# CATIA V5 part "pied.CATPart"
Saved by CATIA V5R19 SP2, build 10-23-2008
Part number: pose pied
Bounding box of the stored display mesh (mm): x -13.5 to 13.5, y -11.25 to 6.521, z -13.5 to 67.5
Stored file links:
  F:\Travaux\Modélisations\CFAO_2011\MMS\MMS_GR2\AA_OK\jboiteux\Catia\pied.CATPart
  F:\Travaux\Modélisations\CFAO_2011\MMS\MMS_GR2\AA_OK\jboiteux\Catia\boulon gauche.CATPart
  F:\Travaux\Modélisations\CFAO_2011\MMS\MMS_GR2\AA_OK\jboiteux\Catia\bati.CATPart
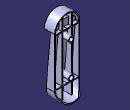
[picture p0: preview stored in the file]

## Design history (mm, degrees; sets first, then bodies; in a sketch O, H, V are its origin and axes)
Parameters
  `rayon ext` = 4.5 mm {= External.royontubebati /2}
External parameters (linked from other documents)
  External.rayontube = 9 mm
  External.royontubebati = 9 mm
Body1 (main body)
  Sketch1 on zx-plane, origin (0, 0, 0), H (-1, 0, 0), V (0, 0, 1)
    arc A1 centre (0, 54) radius 13.5 from (13.5, 54) to (-13.5, 54) ccw
    point P1 (0, 54)
    point P2 (0, 67.5)
    arc A2 centre (0, 0) radius 13.5 from (-13.5, 0) to (13.5, 0) ccw
    point P3 (0, 0)
    point P4 (0, -13.5)
    line L1 (-13.5, 54) -> (-13.5, 0)
    point P5 (-13.5, 0)
    line L2 (13.5, 0) -> (13.5, 54)
    point P7 (13.5, 0)
    point P9 (-13.5, 0)
    point P10 (13.5, 0)
    radius A1 = 13.5 {= `rayon ext` *3}
    distance A1 A2 = 81 {= `rayon ext` *18}
    distance P3 O = 0
    distance L2 L1 = 27 {= 6*`rayon ext`}
    radius A2 = 13.5 {= 3*`rayon ext`}
    coincidence: P1 V, A1 P2, P2 V, P3 V, A2 P4, P4 V, P5 A2, L2 P10, L1 P9, P5 P9, P7 P10
    tangency: L1 A2, L2 A1
  Sketch2 on yz-plane, origin (0, 0, 0), H (0, 1, 0), V (0, 0, 1)
    line L1 (6.5212, -13.5) -> (-10.3538, -13.5)
    line L2 (-10.3538, -13.5) -> (-4.5, 53.4095)
    point P3 (-4.5, 53.4095)
    line L3 (-4.5, 53.4095) -> (-11.25, 54)
    line L4 (-11.25, 54) -> (-11.25, 67.5)
    line L5 (-11.25, 67.5) -> (0, 67.5)
    point P6 (0, 67.5)
    line L6 (0, 67.5) -> (0, 0)
    point P7 (0, 0)
    line L7 (6.5212, -11.25) -> (6.5212, -13.5)
    point P8 (6.5212, -11.25)
    spline S1 through (6.5212, -11.25) (2.0212, -6.75) (0, 0)
    point P9 (6.5212, -11.25)
    point P10 (0, 0)
    point P11 (2.0212, -6.75)
    distance L5 L1 = 81 {= 18*`rayon ext`}
    angle L4 L3 = 95
    distance L5 H = 67.5 {= 15*`rayon ext`}
    distance P3 L4 = 6.75 {= `rayon ext` *3/2}
    length L1 = 16.875 {= `rayon ext` *15/4}
    length L5 = 11.25 {= `rayon ext`* 5/2}
    length L7 = 2.25 {= `rayon ext` /2}
    distance P7 O = 0
    length L4 = 13.5 {= 3*`rayon ext`}
    distance L7 P11 = 4.5 {= `rayon ext`}
    distance P11 L1 = 6.75 {= `rayon ext` *1.5}
    horizontal: L1 H, L5 H
    perpendicularity: L3 L2
    vertical: L4 V, L7 V
    coincidence: P6 V, P9 P8, P10 O
  SolidCombine1: FirstComponentDirection Sketch1, FirstComponentProfile Sketch1, SecondComponentDirection Sketch2, SecondComponentProfile Sketch2
  Sketch3 on face of SolidCombine1 from Sketch2.L4, origin (0, -11.25, 0), H (1, 0, 0), V (0, 0, 1)
    arc A1 centre (0, 42.0941) radius 18 from (13.5, 54) to (-13.5, 54) ccw
    point P1 (0, 42.0941)
    reference projected point E1 (13.5, 54) from vertex [face of SolidCombine1 from Sketch2.L4 | face of SolidCombine1 from Sketch1.A1 | face of SolidCombine1 from Sketch2.L3 | face of SolidCombine1 from Sketch1.L1]
    projected line E2 (-13.5, 53.4095) -> (13.5, 53.4095) from edge [face of SolidCombine1 from Sketch2.L2 | face of SolidCombine1 from Sketch2.L3]
    line L1 (-13.5, 53.4095) -> (-13.5, 54)
    line L2 (13.5, 53.4095) -> (13.5, 54)
    distance A1 E1 = 0
    radius A1 = 18 {= 4*`rayon ext`}
    angle L1 E2 = 90
    angle E2 L2 = 90
    coincidence: P1 V
  Pocket1: profile Sketch3, direction (0, 1, 0), up to face of SolidCombine1 from Sketch2.L2
  Shell1: ExtOffset 0, Face (face of SolidCombine1 from Sketch2.L6; face of SolidCombine1 from Sketch2.S1; face of SolidCombine1 from Sketch2.L7), IntOffset 1
  Sketch4 on face of SolidCombine1 from Sketch2.L6, origin (0, 0, 0), H (-1, 0, 0), V (0, 0, 1)
    projected arc E1 centre (0, 54) radius 12.5 from (12.5, 54) to (-12.5, 54) ccw from edge [face of SolidCombine1 from Sketch2.L6 | face of Shell1]
    projected arc E2 centre (0, 54) radius 12.5 from (-4.75, 65.5623) to (-5.75, 65.099) ccw from edge [face of SolidCombine1 from Sketch2.L6 | face of Shell1]
    point P1 (12.5, 54)
    point P2 (-12.5, 54)
    projected arc E3 centre (0, 0) radius 12.5 from (-5.4486, -11.25) to (5.4486, -11.25) ccw from edge [face of Shell1 | face of SolidCombine1 from Sketch2.L7]
    projected arc E4 centre (0, 0) radius 12.5 from (-5.75, -11.099) to (-4.75, -11.5623) ccw from edge [face of Shell1 | face of SolidCombine1 from Sketch2.L7]
    point P3 (-5.4486, -11.25)
    point P4 (5.4486, -11.25)
    projected line E5 (-12.5, 54) -> (-12.5, 0) from edge [face of SolidCombine1 from Sketch2.L6 | face of Shell1]
    projected line E6 (-12.5, 2) -> (-12.5, 1) from edge [face of SolidCombine1 from Sketch2.L6 | face of Shell1]
    point P5 (-12.5, 54)
    point P6 (-12.5, 0)
    point P7 (-5.75, 65.099)
    line L1 (-5.75, 65.099) -> (-5.75, 53)
    point P8 (-5.75, 53)
    line L2 (-5.75, 53) -> (-12.4599, 53)
    point P9 (-12.4599, 53)
    point P10 (-12.5, 52)
    line L3 (-12.5, 52) -> (-5.75, 52)
    point P11 (-5.75, 52)
    line L4 (-5.75, 52) -> (-5.75, 2)
    point P12 (-5.75, 2)
    line L5 (-5.75, 2) -> (-12.5, 2)
    point P13 (-12.5, 2)
    point P14 (-12.5, 1)
    line L6 (-12.5, 1) -> (-5.75, 1)
    point P15 (-5.75, 1)
    line L7 (-5.75, 1) -> (-5.75, -11.099)
    point P16 (-5.75, -11.099)
    point P17 (-4.75, -11.5623)
    line L8 (-4.75, -11.5623) -> (-4.75, 1)
    point P18 (-4.75, 1)
    line L9 (-4.75, 1) -> (0, 1)
    point P19 (0, 1)
    point P20 (0, 2)
    line L10 (0, 2) -> (-4.75, 2)
    point P21 (-4.75, 2)
    line L11 (-4.75, 2) -> (-4.75, 52)
    point P22 (-4.75, 52)
    line L12 (-4.75, 52) -> (0, 52)
    point P23 (0, 52)
    point P24 (0, 53)
    line L13 (0, 53) -> (-4.75, 53)
    point P25 (-4.75, 53)
    line L14 (-4.75, 53) -> (-4.75, 65.5623)
    point P26 (-4.75, 65.5623)
    line L15 (-12.4599, 53) -> (-12.5, 52)
    point P27 (4.75, 52)
    point P28 (4.75, 2)
    line L16 (4.75, 2) -> (4.75, 52)
    point P29 (0, 1)
    point P30 (4.75, 1)
    line L17 (4.75, 1) -> (0, 1)
    point P31 (4.75, 2)
    point P32 (0, 2)
    line L18 (0, 2) -> (4.75, 2)
    point P33 (4.75, 1)
    point P34 (4.75, -11.5623)
    line L19 (4.75, -11.5623) -> (4.75, 1)
    point P35 (5.75, -11.099)
    point P36 (5.75, 1)
    line L20 (5.75, 1) -> (5.75, -11.099)
    point P37 (-5.4486, -11.25)
    point P38 (5.4486, -11.25)
    point P39 (4.75, -11.5623)
    construction arc A1 centre (0, 0) radius 12.5 from (5.4486, -11.25) to (-5.4486, -11.25) cw
    arc A2 centre (0, 0) radius 12.5 from (5.75, -11.099) to (4.75, -11.5623) cw
    point P40 (5.75, 1)
    point P41 (12.5, 1)
    line L21 (12.5, 1) -> (5.75, 1)
    point P42 (12.5, 2)
    point P43 (5.75, 2)
    line L22 (5.75, 2) -> (12.5, 2)
    point P44 (12.5, 0)
    point P45 (12.5, 54)
    point P46 (12.5, 1)
    point P47 (12.5, 2)
    construction line L23 (12.5, 54) -> (12.5, 0)
    line L24 (12.5, 2) -> (12.5, 1)
    point P48 (5.75, 2)
    point P49 (5.75, 52)
    line L25 (5.75, 52) -> (5.75, 2)
    point P50 (0, 52)
    point P51 (4.75, 52)
    line L26 (4.75, 52) -> (0, 52)
    point P52 (4.75, 53)
    point P53 (0, 53)
    line L27 (0, 53) -> (4.75, 53)
    point P54 (5.75, 52)
    point P55 (12.5, 52)
    line L28 (12.5, 52) -> (5.75, 52)
    point P56 (12.4599, 53)
    point P57 (5.75, 53)
    line L29 (5.75, 53) -> (12.4599, 53)
    point P58 (4.75, 65.5623)
    point P59 (4.75, 53)
    line L30 (4.75, 53) -> (4.75, 65.5623)
    point P60 (5.75, 53)
    point P61 (5.75, 65.099)
    line L31 (5.75, 65.099) -> (5.75, 53)
    point P62 (12.5, 54)
    point P63 (-12.5, 54)
    point P64 (5.75, 65.099)
    point P65 (4.75, 65.5623)
    construction arc A3 centre (0, 54) radius 12.5 from (-12.5, 54) to (12.5, 54) cw
    arc A4 centre (0, 54) radius 12.5 from (4.75, 65.5623) to (5.75, 65.099) cw
    point P66 (12.5, 52)
    point P67 (12.4599, 53)
    line L32 (12.4599, 53) -> (12.5, 52)
    distance L1 L14 = 1
    distance L2 L3 = 1
    distance L9 L10 = 1
    distance L6 L5 = 1
    distance E1 L13 = 13.5 {= 3*`rayon ext`}
    distance L6 E3 = 13.5 {= 3*`rayon ext`}
    distance E5 L4 = 6.75 {= 1.5*`rayon ext`}
    distance L7 L8 = 1
    coincidence: P7 E1, P9 E1, P10 E5, P11 L1, P13 E5, P14 E5, P16 E3, P17 E3, P19 V, P20 L5, P20 V, P21 L8, P22 L3, P24 V, P24 L2, P25 L11, P26 E1, P19 P29, P20 P32, P23 P50, P24 P53, P27 P51, P28 P31, P30 P33, P34 P39, P36 P40, P41 P46, P42 P47, P43 P48, P49 P54, P52 P59, P55 P66, P56 P67, P57 P60, P58 P65, P61 P64
    vertical: L1 V, L4 V, L7 V, L8 V, L11 V, L14 V
    horizontal: L2 H, L3 H, L5 H, L6 H, L9 H, L10 H, L12 H, L13 H
    symmetry: P22 P27 V, P21 P28 V, L11 L16 V, P19 P29 V, P18 P30 V, L9 L17 V, P21 P31 V, P20 P32 V, L10 L18 V, P18 P33 V, P17 P34 V, L8 L19 V, P16 P35 V, P15 P36 V, L7 L20 V, P4 P37 V, P3 P38 V, P17 P39 V, E3 A1 V, E3 A2 V, P15 P40 V, P14 P41 V, L6 L21 V, P13 P42 V, P12 P43 V, L5 L22 V, P6 P44 V, P5 P45 V, P14 P46 V, P13 P47 V, E5 L23 V, E5 L24 V, P12 P48 V, P11 P49 V, L4 L25 V, P23 P50 V, P22 P51 V, L12 L26 V, P25 P52 V, P24 P53 V, L13 L27 V, P11 P54 V, P10 P55 V, L3 L28 V, P9 P56 V, P8 P57 V, L2 L29 V, P26 P58 V, P25 P59 V, L14 L30 V, P8 P60 V, P7 P61 V, L1 L31 V, P2 P62 V, P1 P63 V, P7 P64 V, P26 P65 V, E1 A3 V, E1 A4 V, P10 P66 V, P9 P67 V, L15 L32 V
  Pad1: profile Sketch4, direction (0, 1, 0), up to face of Shell1
  Sketch5 on face of SolidCombine1, origin (0, -9.103, 0.7964), H (1, 0, 0), V (0, 0.0872, 0.9962)
    circle A1 centre (-11.25, 2.25) radius 1.125
    point P1 (-11.25, 2.25)
    reference projected line E1 (-13.5, -3.5531) -> (-13.5, 234.7289) from edge [face of SolidCombine1 | face of SolidCombine1 from Sketch1.L2]
    distance E1 P1 = 2.25 {= `rayon ext` /2}
    radius A1 = 1.125 {= `rayon ext` /4}
    distance H P1 = 2.25 {= `rayon ext` /2}
  Pad2: profile Sketch5, direction (0, -0.9962, 0.0872), length 0.45 {= `rayon ext` /10}
  RectPattern1: of Pad2, direction 1 instances 12, spacing 4.5 {= `rayon ext`}, along edge [face of SolidCombine1 from Sketch1.L1 | face of SolidCombine1], direction 2 instances 7, spacing 3.735 {= `rayon ext` *83/100}, along edge [face of Pad1 from Sketch4.L28 | face of Pad1] reversed
  Sketch6 on face of Pad1, origin (0, 0, 0), H (-1, 0, 0), V (0, 0, 1)
    circle A1 centre (0, 45) radius 2.25
    point P1 (0, 45)
    circle A2 centre (0, 45) radius 3.15
    circle A3 centre (0, 9) radius 3.15
    point P2 (0, 9)
    circle A4 centre (0, 9) radius 2.25
    reference projected arc E1 centre (0, 0) radius 13.5 from (-13.5, 0) to (13.5, 0) ccw from edge [face of SolidCombine1 from Sketch1.A2 | face of SolidCombine1]
    radius A1 = 2.25 {= `rayon ext` /2}
    radius A2 = 3.15 {= `rayon ext` *7/10}
    radius A4 = 2.25 {= `rayon ext` /2}
    radius A3 = 3.15 {= `rayon ext` *7/10}
    distance V P1 = 0
    distance V P2 = 0
    distance E1 P2 = 22.5 {= `rayon ext` *5}
    distance P1 P2 = 36 {= `rayon ext` *8}
  Pad3: profile Sketch6, direction (0, 1, 0), length 4.5 {= `rayon ext`}, opposite side up to face of Shell1
Relations
  RectPattern1.Nb1 = 12 (deactivated)
  Sketch4.distance(L2 L3) = `rayon ext` *3/20 (deactivated)
  RectPattern1.Nb1 = `rayon ext` *3/5 (deactivated)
